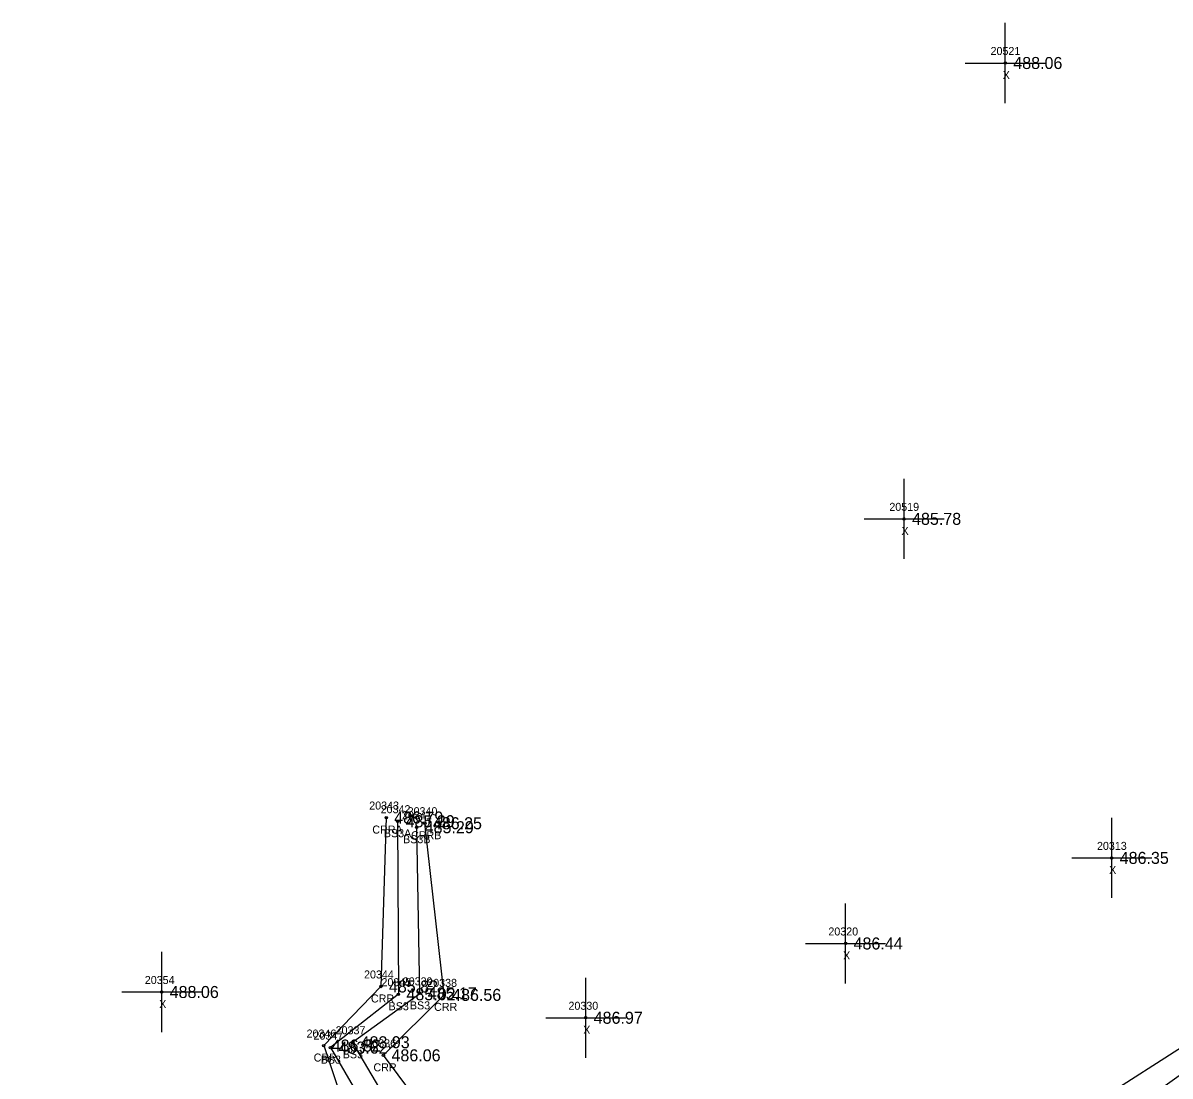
# Model space of a CAD drawing. Extents: x 1649406 to 1650436, y 896752 to 898178.
# Drawn here: x 1649688.5 to 1649831.9, y 897420.5 to 897552 of the extents above; entities that cross this region are included whole.
import ezdxf

# ---------------------------------------------------------------- set-up
doc = ezdxf.new("R2010")
doc.units = 0
for name, color, linetype in [('RD_DTM_BkLn2', 7, 'Continuous'), ('RD_DTM_BkLn_txCode', 7, 'Continuous'), ('RD_EX_H2O', 7, 'Continuous'), ('RD_EX_H2O_txCode', 7, 'Continuous'), ('RD_EX_Misc', 7, 'Continuous'), ('RD_EX_Misc_txCode', 7, 'Continuous'), ('RD_EX_TX_H2O_ELEV', 7, 'Continuous'), ('RD_EX_TX_Misc_ELEV', 7, 'Continuous'), ('RD_SMD_Locator', 7, 'Continuous')]:
    doc.layers.add(name, color=color, linetype=linetype)

msp = doc.modelspace()

# ---------------------------------------------------------------- linework, layer by layer
at = {"layer": 'RD_DTM_BkLn2'}
for points in [[(1649735.32, 897452.32), (1649735.42, 897430.71), (1649726.93, 897424.04), (1649733.64, 897412.51), (1649739.22, 897406.36), (1649710.88, 897394.12), (1649696.6, 897378.36), (1649634.62, 897385.73), (1649610.45, 897366.7), (1649591.79, 897363.75), (1649561.2, 897371.75), (1649517.81, 897366.5), (1649502.21, 897346.17), (1649434.27, 897348.24)], [(1649868.3, 897435.39), (1649845.55, 897429.41), (1649825.91, 897415.47), (1649821.11, 897400.31), (1649799.74, 897406.72), (1649785.82, 897395.65), (1649747.09, 897406.73), (1649737.33, 897411.73), (1649729.69, 897424.71), (1649738.08, 897430.82), (1649737.7, 897451.57)]]:
    msp.add_lwpolyline(points, dxfattribs=at)
at = {"layer": 'RD_EX_H2O'}
for points in [[(1649733.89, 897452.78), (1649733.23, 897431.68), (1649726.08, 897424.3), (1649730.38, 897411.38), (1649709.93, 897395.57), (1649696.43, 897381.39), (1649633.87, 897388.98), (1649608.54, 897369.49), (1649592.36, 897367.34), (1649564.26, 897376.33), (1649519.76, 897372.2), (1649499.24, 897352.4), (1649435.41, 897352.44)], [(1649868.8, 897437.77), (1649846.16, 897432.3), (1649822.76, 897417.33), (1649816.54, 897408.15), (1649799.76, 897408.66), (1649785.38, 897398.06), (1649752.08, 897411.48), (1649746.25, 897411.21), (1649738.94, 897415.88), (1649733.55, 897423.08), (1649741.13, 897430.63), (1649738.72, 897452.07)]]:
    msp.add_lwpolyline(points, dxfattribs=at)
at = {"layer": 'RD_EX_Misc'}
for p, q in [((1649811.26, 897542.03), (1649811.26, 897552.03)), ((1649806.26, 897547.03), (1649816.26, 897547.03)), ((1649798.61, 897485.09), (1649798.61, 897495.09)), ((1649793.61, 897490.09), (1649803.61, 897490.09)), ((1649824.56, 897442.74), (1649824.56, 897452.74)), ((1649819.56, 897447.74), (1649829.56, 897447.74)), ((1649791.3, 897432.05), (1649791.3, 897442.05)), ((1649786.3, 897437.05), (1649796.3, 897437.05)), ((1649705.83, 897425.99), (1649705.83, 897435.99)), ((1649758.82, 897422.77), (1649758.82, 897432.77)), ((1649700.83, 897430.99), (1649710.83, 897430.99)), ((1649753.82, 897427.77), (1649763.82, 897427.77))]:
    msp.add_line(p, q, dxfattribs=at)
at = {"layer": 'RD_SMD_Locator'}
for centre in [(1649811.26, 897547.03), (1649798.61, 897490.09), (1649733.89, 897452.78), (1649735.32, 897452.32), (1649737.7, 897451.57), (1649738.72, 897452.07), (1649824.56, 897447.74), (1649791.3, 897437.05), (1649705.83, 897430.99), (1649733.23, 897431.68), (1649738.08, 897430.82), (1649735.42, 897430.71), (1649741.13, 897430.63), (1649758.82, 897427.77), (1649726.08, 897424.3), (1649726.93, 897424.04), (1649729.69, 897424.71), (1649733.55, 897423.08)]:
    msp.add_circle(centre, 0.15, dxfattribs=at)

# ---------------------------------------------------------------- texts
at = {"layer": 'RD_DTM_BkLn_txCode'}
for s, p in [('20342', (1649733.2, 897453.32)), ('20341', (1649735.87, 897452.57)), ('BS3A', (1649733.6, 897450.32)), ('BS3B', (1649736, 897449.57)), ('20345', (1649733.3, 897431.71)), ('20339', (1649735.96, 897431.82)), ('BS3', (1649734.19, 897428.71)), ('BS3', (1649736.85, 897428.82)), ('20337', (1649727.57, 897425.71)), ('20347', (1649724.81, 897425.04)), ('BS3', (1649728.46, 897422.71)), ('BS3', (1649725.7, 897422.04))]:
    msp.add_text(s, height=1, dxfattribs=at).set_placement(p)
at = {"layer": 'RD_EX_H2O_txCode'}
for s, p in [('20343', (1649731.77, 897453.78)), ('20340', (1649736.57, 897453.07)), ('CRRA', (1649732.15, 897450.78)), ('CRRB', (1649737, 897450.07)), ('20344', (1649731.12, 897432.68)), ('20338', (1649739.02, 897431.63)), ('CRR', (1649731.98, 897429.68)), ('CRR', (1649739.88, 897428.63)), ('20346', (1649723.94, 897425.3)), ('20336', (1649731.41, 897424.08)), ('CRR', (1649724.83, 897422.3)), ('CRR', (1649732.3, 897421.08))]:
    msp.add_text(s, height=1, dxfattribs=at).set_placement(p)
at = {"layer": 'RD_EX_Misc_txCode'}
for s, p in [('20521', (1649809.42, 897548.03)), ('X', (1649810.94, 897545.03)), ('20519', (1649796.77, 897491.09)), ('X', (1649798.29, 897488.09)), ('20313', (1649822.72, 897448.74)), ('X', (1649824.24, 897445.74)), ('20320', (1649789.15, 897438.05)), ('X', (1649790.99, 897435.05)), ('20354', (1649703.72, 897431.99)), ('X', (1649705.52, 897428.99)), ('20330', (1649756.67, 897428.77)), ('X', (1649758.51, 897425.77))]:
    msp.add_text(s, height=1, dxfattribs=at).set_placement(p)
at = {"layer": 'RD_EX_TX_H2O_ELEV'}
for s, p in [('486.79', (1649734.89, 897452.03)), ('486.25', (1649739.72, 897451.32)), ('485.82', (1649734.23, 897430.93)), ('486.56', (1649742.13, 897429.88)), ('486.82', (1649727.08, 897423.55)), ('486.06', (1649734.55, 897422.33))]:
    msp.add_text(s, height=1.5, dxfattribs=at).set_placement(p)
at = {"layer": 'RD_EX_TX_Misc_ELEV'}
for s, p in [('488.06', (1649812.26, 897546.28)), ('485.78', (1649799.61, 897489.34)), ('485.29', (1649736.32, 897451.57)), ('485.29', (1649738.7, 897450.82)), ('486.35', (1649825.56, 897446.99)), ('486.44', (1649792.3, 897436.3)), ('488.06', (1649706.83, 897430.24)), ('485.02', (1649736.42, 897429.96)), ('485.17', (1649739.08, 897430.07)), ('486.97', (1649759.82, 897427.02)), ('483.93', (1649730.69, 897423.96)), ('483.62', (1649727.93, 897423.29))]:
    msp.add_text(s, height=1.5, dxfattribs=at).set_placement(p)

doc.saveas('drawing.dxf')
